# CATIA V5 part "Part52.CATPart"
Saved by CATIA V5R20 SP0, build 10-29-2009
Part number: FA 042200-2
Revision: ANY
Definition: UNKNOWN
Nomenclature: FA 042200-2
Source: Unknown
Bounding box of the stored display mesh (mm): x -1.5 to 1.5, y 0 to 2.7, z -1.5 to 1.5
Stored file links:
  C:\Users\Utente\Desktop\IO LAVORO\3D X SITO CF\CUMSA\3D files FA\FA 042204-21\Part52.CATPart

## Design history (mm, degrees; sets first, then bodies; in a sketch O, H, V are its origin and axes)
Body1 "Cortar-Extruir1" (main body)
  Solid1: solid without history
